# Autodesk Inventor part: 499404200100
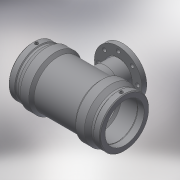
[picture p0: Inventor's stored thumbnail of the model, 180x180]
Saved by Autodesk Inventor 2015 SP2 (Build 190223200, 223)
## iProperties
Created: 2017-06
Part Number: 499404200100
Material: Generic
Description: PLASSON FLANGED TEE 200x100x200
Document SubType Name: Modeling
Designer: KIM
Mass: 57.3761 g
Surface Area: 241.06 cm^2
Volume: 57.3761 cm^3
Density: 1 g/cm^3
Appearance: Default
Author: KIM
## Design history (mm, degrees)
derived "499404.ipt"
feature "Solid1::499404.ipt"
tag "TaggingFeature1"
body "Solid1"
other parameters: "d13" = 451, "d14" = 17.6296, "d19" = 3.52592, "d20" = 168 deg, "d22" = 242.73, "d23" = 261, "d24" = 235.4481, "d25" = 135 deg, "d26" = 315.7, "d27" = 135 deg, "d29" = 125, "d35" = 15, "d39" = 5 deg, "d45" = 4, "d46" = 14, "d47" = 0, "d48" = -245, "d55" = 234.9, "d56" = 261, "d57" = 157.85, "d58" = 135 deg, "d59" = 114, "d60" = 114, "d61" = 135 deg, "d62" = 245, "d72" = 205.205, "d73" = 102.6025, "d74" = -245, "d84" = 245, "d87" = 158, "d90" = 125, "d91" = 15 deg, "d93" = 22, "d95" = 4.74, "d97" = 18, "d100" = 0, "d102" = 360 deg, "d105" = 0, "d107" = 0, "d108" = 3, "d109" = 0, "d110" = 34.2, "d111" = 11.4, "L_" = 451, "L_1" = 114, "D_" = 261, "A_" = 125, "d_2" = 12, "H_" = 245, "t_" = 22, "d_1" = 158, "s_" = 18
